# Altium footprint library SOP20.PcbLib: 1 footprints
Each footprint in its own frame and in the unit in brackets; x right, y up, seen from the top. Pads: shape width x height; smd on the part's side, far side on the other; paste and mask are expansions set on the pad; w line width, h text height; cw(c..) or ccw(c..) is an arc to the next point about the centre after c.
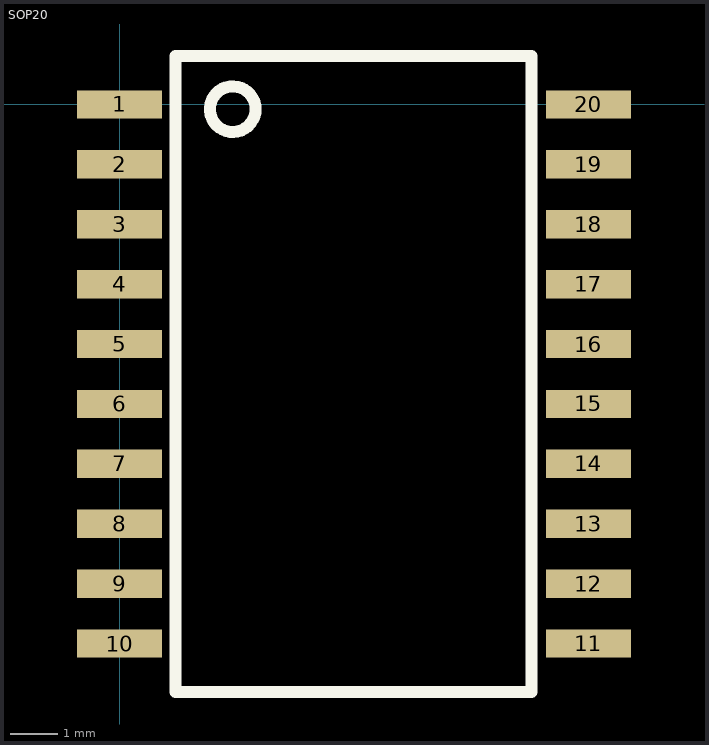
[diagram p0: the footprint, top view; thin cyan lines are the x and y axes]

## SOP20 [mm]
pads (20):
  rect 1.8x0.6 smd: 1(0,0) 2(0,-1.27) 3(0,-2.54) 4(0,-3.81) 5(0,-5.08) 6(0,-6.35) 7(0,-7.62) 8(0,-8.89) 9(0,-10.16) 10(0,-11.43) 11(9.94,-11.43) 12(9.94,-10.16) 13(9.94,-8.89) 14(9.94,-7.62) 15(9.94,-6.35) 16(9.94,-5.08) 17(9.94,-3.81) 18(9.94,-2.54) 19(9.94,-1.27) 20(9.94,0)
Top Overlay:
  circle w0.254: c2.4,-0.1 r0.484
  lines w0.254: 1.19,-12.46 8.73,-12.46 8.73,1.03 1.19,1.03 1.19,-12.46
